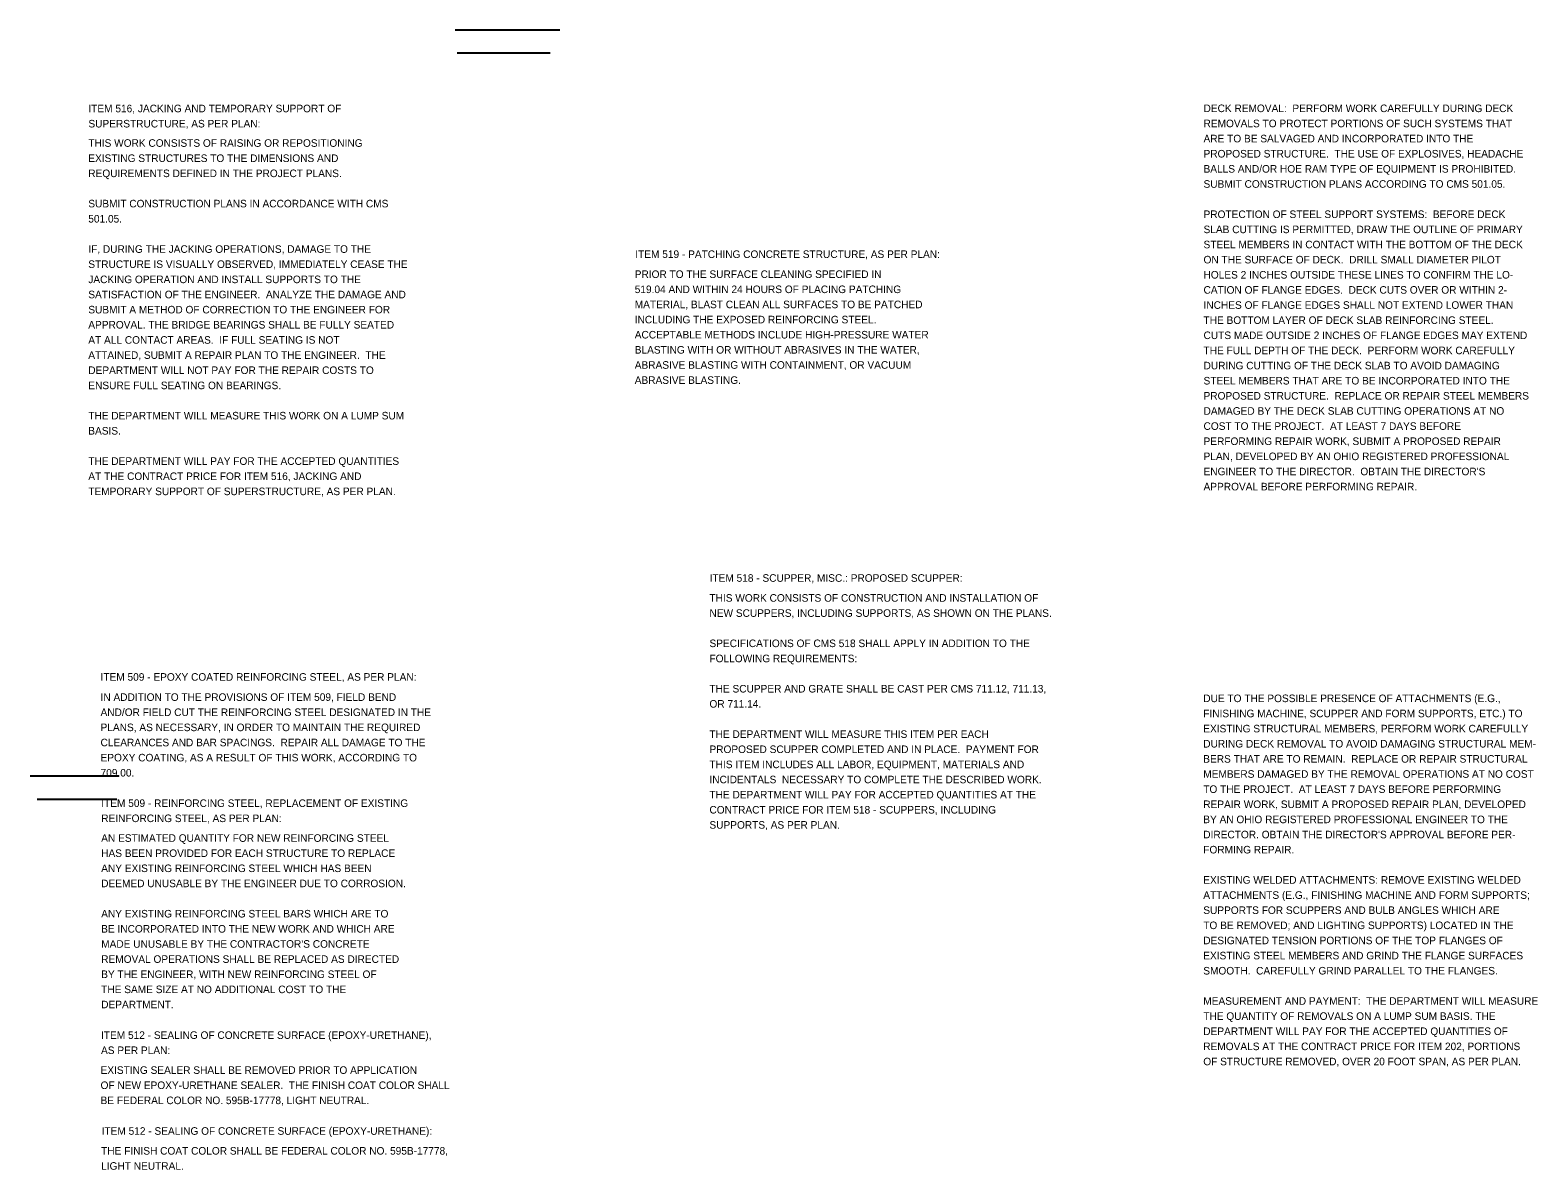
# Model space of a CAD drawing. Extents: x 8.9 to 72, y -18.6 to 3.4.
# Drawn here: x 44.1 to 72, y -17.7 to 3.39 of the extents above; entities that cross this region are included whole.
import ezdxf

# ---------------------------------------------------------------- set-up
doc = ezdxf.new("R2010")
doc.units = 0
doc.layers.add('BR_P_Gen_Text', color=7, linetype='Continuous')
doc.layers.add('SH_Text', color=7, linetype='Continuous')

msp = doc.modelspace()

# ---------------------------------------------------------------- linework, layer by layer
at = {"layer": 'BR_P_Gen_Text'}
for p, q in [((53.902, 3.39), (51.97, 3.39)), ((53.725, 2.963), (52.003, 2.963)), ((45.746, -10.413), (44.102, -10.413)), ((45.709, -10.844), (44.234, -10.844))]:
    msp.add_line(p, q, dxfattribs=at)

# ---------------------------------------------------------------- texts
for s, rotation, p in [('ITEM 516, JACKING AND TEMPORARY SUPPORT OF ', 0, (45.18, 1.871)), ('SUPERSTRUCTURE, AS PER PLAN:', 0, (45.18, 1.59)), ('THIS WORK CONSISTS OF RAISING OR REPOSITIONING ', 0, (45.178, 1.232)), ('EXISTING STRUCTURES TO THE DIMENSIONS AND ', 0, (45.178, 0.951)), ('REQUIREMENTS DEFINED IN THE PROJECT PLANS.', 0, (45.178, 0.671)), ('SUBMIT CONSTRUCTION PLANS IN ACCORDANCE WITH CMS ', 0, (45.178, 0.111)), ('501.05.', 0, (45.178, -0.17)), ('IF, DURING THE JACKING OPERATIONS, DAMAGE TO THE ', 0, (45.178, -0.73)), ('STRUCTURE IS VISUALLY OBSERVED, IMMEDIATELY CEASE THE ', 0, (45.178, -1.01)), ('PRIOR TO THE SURFACE CLEANING SPECIFIED IN ', 359.9999, (55.291, -1.195)), ('JACKING OPERATION AND INSTALL SUPPORTS TO THE ', 0, (45.178, -1.291)), ('519.04 AND WITHIN 24 HOURS OF PLACING PATCHING ', 359.9999, (55.291, -1.475)), ('SATISFACTION OF THE ENGINEER.  ANALYZE THE DAMAGE AND ', 0, (45.178, -1.571)), ('MATERIAL, BLAST CLEAN ALL SURFACES TO BE PATCHED ', 359.9999, (55.291, -1.755)), ('SUBMIT A METHOD OF CORRECTION TO THE ENGINEER FOR ', 0, (45.178, -1.851)), ('INCLUDING THE EXPOSED REINFORCING STEEL.  ', 359.9999, (55.291, -2.035)), ('APPROVAL. THE BRIDGE BEARINGS SHALL BE FULLY SEATED ', 0, (45.178, -2.131)), ('ACCEPTABLE METHODS INCLUDE HIGH-PRESSURE WATER ', 359.9999, (55.291, -2.315)), ('AT ALL CONTACT AREAS.  IF FULL SEATING IS NOT ', 0, (45.178, -2.412)), ('BLASTING WITH OR WITHOUT ABRASIVES IN THE WATER, ', 359.9999, (55.291, -2.595)), ('ATTAINED, SUBMIT A REPAIR PLAN TO THE ENGINEER.  THE ', 0, (45.178, -2.692)), ('ABRASIVE BLASTING WITH CONTAINMENT, OR VACUUM ', 359.9999, (55.291, -2.875)), ('DEPARTMENT WILL NOT PAY FOR THE REPAIR COSTS TO ', 0, (45.178, -2.972)), ('ABRASIVE BLASTING.', 359.9999, (55.291, -3.155)), ('ENSURE FULL SEATING ON BEARINGS.', 0, (45.178, -3.253)), ('THE DEPARTMENT WILL MEASURE THIS WORK ON A LUMP SUM ', 0, (45.178, -3.813)), ('BASIS.', 0, (45.178, -4.093)), ('THE DEPARTMENT WILL PAY FOR THE ACCEPTED QUANTITIES ', 0, (45.178, -4.654)), ('AT THE CONTRACT PRICE FOR ITEM 516, JACKING AND ', 0, (45.178, -4.934)), ('TEMPORARY SUPPORT OF SUPERSTRUCTURE, AS PER PLAN.', 0, (45.178, -5.214)), ('AN ESTIMATED QUANTITY FOR NEW REINFORCING STEEL ', 359.9999, (45.417, -11.629)), ('HAS BEEN PROVIDED FOR EACH STRUCTURE TO REPLACE ', 359.9999, (45.417, -11.909)), ('ANY EXISTING REINFORCING STEEL WHICH HAS BEEN ', 359.9999, (45.417, -12.189)), ('DEEMED UNUSABLE BY THE ENGINEER DUE TO CORROSION.', 359.9999, (45.417, -12.469)), ('ANY EXISTING REINFORCING STEEL BARS WHICH ARE TO ', 359.9999, (45.417, -13.029)), ('BE INCORPORATED INTO THE NEW WORK AND WHICH ARE ', 359.9999, (45.417, -13.309)), ("MADE UNUSABLE BY THE CONTRACTOR'S CONCRETE ", 359.9999, (45.417, -13.589)), ('REMOVAL OPERATIONS SHALL BE REPLACED AS DIRECTED ', 359.9999, (45.417, -13.869)), ('BY THE ENGINEER, WITH NEW REINFORCING STEEL OF ', 359.9999, (45.417, -14.149)), ('THE SAME SIZE AT NO ADDITIONAL COST TO THE ', 359.9999, (45.417, -14.429)), ('DEPARTMENT.', 359.9999, (45.417, -14.709))]:
    msp.add_text(s, height=0.14, rotation=rotation, dxfattribs=at).set_placement(p)
for s, p in [('DECK REMOVAL:  PERFORM WORK CAREFULLY DURING DECK', (65.818, 1.874)), ('REMOVALS TO PROTECT PORTIONS OF SUCH SYSTEMS THAT ', (65.818, 1.594)), ('ARE TO BE SALVAGED AND INCORPORATED INTO THE ', (65.818, 1.314)), ('PROPOSED STRUCTURE.  THE USE OF EXPLOSIVES, HEADACHE ', (65.818, 1.034)), ('BALLS AND/OR HOE RAM TYPE OF EQUIPMENT IS PROHIBITED.  ', (65.818, 0.754)), ('SUBMIT CONSTRUCTION PLANS ACCORDING TO CMS 501.05.', (65.818, 0.474)), ('PROTECTION OF STEEL SUPPORT SYSTEMS:  BEFORE DECK', (65.818, -0.086)), ('SLAB CUTTING IS PERMITTED, DRAW THE OUTLINE OF PRIMARY', (65.818, -0.366)), ('STEEL MEMBERS IN CONTACT WITH THE BOTTOM OF THE DECK', (65.818, -0.646)), ('ITEM 519 - PATCHING CONCRETE STRUCTURE, AS PER PLAN:', (55.301, -0.825)), ('ON THE SURFACE OF DECK.  DRILL SMALL DIAMETER PILOT', (65.818, -0.926)), ('HOLES 2 INCHES OUTSIDE THESE LINES TO CONFIRM THE LO-', (65.818, -1.206)), ('CATION OF FLANGE EDGES.  DECK CUTS OVER OR WITHIN 2-', (65.818, -1.486)), ('INCHES OF FLANGE EDGES SHALL NOT EXTEND LOWER THAN ', (65.818, -1.766)), ('THE BOTTOM LAYER OF DECK SLAB REINFORCING STEEL.  ', (65.818, -2.046)), ('CUTS MADE OUTSIDE 2 INCHES OF FLANGE EDGES MAY EXTEND ', (65.818, -2.326)), ('THE FULL DEPTH OF THE DECK.  PERFORM WORK CAREFULLY ', (65.818, -2.606)), ('DURING CUTTING OF THE DECK SLAB TO AVOID DAMAGING ', (65.818, -2.886)), ('STEEL MEMBERS THAT ARE TO BE INCORPORATED INTO THE ', (65.818, -3.166)), ('PROPOSED STRUCTURE.  REPLACE OR REPAIR STEEL MEMBERS ', (65.818, -3.446)), ('DAMAGED BY THE DECK SLAB CUTTING OPERATIONS AT NO ', (65.818, -3.726)), ('COST TO THE PROJECT.  AT LEAST 7 DAYS BEFORE ', (65.818, -4.006)), ('PERFORMING REPAIR WORK, SUBMIT A PROPOSED REPAIR ', (65.818, -4.286)), ('PLAN, DEVELOPED BY AN OHIO REGISTERED PROFESSIONAL', (65.818, -4.566)), ("ENGINEER TO THE DIRECTOR.  OBTAIN THE DIRECTOR'S ", (65.818, -4.846)), ('APPROVAL BEFORE PERFORMING REPAIR.', (65.818, -5.126)), ('ITEM 518 - SCUPPER, MISC.: PROPOSED SCUPPER:', (56.677, -6.817)), ('ITEM 509 - EPOXY COATED REINFORCING STEEL, AS PER PLAN:', (45.405, -8.648)), ('IN ADDITION TO THE PROVISIONS OF ITEM 509, FIELD BEND ', (45.405, -9.021)), ('DUE TO THE POSSIBLE PRESENCE OF ATTACHMENTS (E.G.,', (65.813, -9.044)), ('AND/OR FIELD CUT THE REINFORCING STEEL DESIGNATED IN THE ', (45.405, -9.301)), ('FINISHING MACHINE, SCUPPER AND FORM SUPPORTS, ETC.) TO', (65.813, -9.324)), ('PLANS, AS NECESSARY, IN ORDER TO MAINTAIN THE REQUIRED ', (45.405, -9.581)), ('EXISTING STRUCTURAL MEMBERS, PERFORM WORK CAREFULLY', (65.813, -9.604)), ('CLEARANCES AND BAR SPACINGS.  REPAIR ALL DAMAGE TO THE ', (45.405, -9.861)), ('DURING DECK REMOVAL TO AVOID DAMAGING STRUCTURAL MEM-', (65.813, -9.884)), ('EPOXY COATING, AS A RESULT OF THIS WORK, ACCORDING TO ', (45.405, -10.141)), ('BERS THAT ARE TO REMAIN.  REPLACE OR REPAIR STRUCTURAL', (65.813, -10.164)), ('709.00.', (45.405, -10.421)), ('MEMBERS DAMAGED BY THE REMOVAL OPERATIONS AT NO COST', (65.813, -10.444)), ('TO THE PROJECT.  AT LEAST 7 DAYS BEFORE PERFORMING', (65.813, -10.724)), ('ITEM 509 - REINFORCING STEEL, REPLACEMENT OF EXISTING', (45.418, -10.984)), ('REPAIR WORK, SUBMIT A PROPOSED REPAIR PLAN, DEVELOPED', (65.813, -11.004)), ('REINFORCING STEEL, AS PER PLAN:', (45.418, -11.264)), ('BY AN OHIO REGISTERED PROFESSIONAL ENGINEER TO THE', (65.813, -11.284)), ("DIRECTOR. OBTAIN THE DIRECTOR'S APPROVAL BEFORE PER-", (65.813, -11.564)), ('FORMING REPAIR.', (65.813, -11.844)), ('EXISTING WELDED ATTACHMENTS: REMOVE EXISTING WELDED', (65.813, -12.404)), ('ATTACHMENTS (E.G., FINISHING MACHINE AND FORM SUPPORTS;', (65.813, -12.684)), ('SUPPORTS FOR SCUPPERS AND BULB ANGLES WHICH ARE', (65.813, -12.964)), ('TO BE REMOVED; AND LIGHTING SUPPORTS) LOCATED IN THE', (65.813, -13.244)), ('DESIGNATED TENSION PORTIONS OF THE TOP FLANGES OF', (65.813, -13.524)), ('EXISTING STEEL MEMBERS AND GRIND THE FLANGE SURFACES', (65.813, -13.804)), ('SMOOTH.  CAREFULLY GRIND PARALLEL TO THE FLANGES.', (65.813, -14.084)), ('MEASUREMENT AND PAYMENT:  THE DEPARTMENT WILL MEASURE', (65.813, -14.644)), ('THE QUANTITY OF REMOVALS ON A LUMP SUM BASIS. THE', (65.813, -14.924)), ('DEPARTMENT WILL PAY FOR THE ACCEPTED QUANTITIES OF', (65.813, -15.204)), ('ITEM 512 - SEALING OF CONCRETE SURFACE (EPOXY-URETHANE),', (45.414, -15.276)), ('REMOVALS AT THE CONTRACT PRICE FOR ITEM 202, PORTIONS', (65.813, -15.484)), ('AS PER PLAN:', (45.414, -15.556)), ('OF STRUCTURE REMOVED, OVER 20 FOOT SPAN, AS PER PLAN.', (65.813, -15.764)), ('EXISTING SEALER SHALL BE REMOVED PRIOR TO APPLICATION', (45.405, -15.923)), ('OF NEW EPOXY-URETHANE SEALER.  THE FINISH COAT COLOR SHALL ', (45.405, -16.203)), ('BE FEDERAL COLOR NO. 595B-17778, LIGHT NEUTRAL.', (45.405, -16.483)), ('ITEM 512 - SEALING OF CONCRETE SURFACE (EPOXY-URETHANE):', (45.425, -17.05)), ('THE FINISH COAT COLOR SHALL BE FEDERAL COLOR NO. 595B-17778, ', (45.416, -17.417)), ('LIGHT NEUTRAL.', (45.416, -17.697))]:
    msp.add_text(s, height=0.14, dxfattribs=at).set_placement(p)
at = {"layer": 'SH_Text'}
for s, p in [('THIS WORK CONSISTS OF CONSTRUCTION AND INSTALLATION OF', (56.674, -7.186)), ('NEW SCUPPERS, INCLUDING SUPPORTS, AS SHOWN ON THE PLANS.', (56.674, -7.466)), ('SPECIFICATIONS OF CMS 518 SHALL APPLY IN ADDITION TO THE', (56.674, -8.026)), ('FOLLOWING REQUIREMENTS:', (56.674, -8.306)), ('THE SCUPPER AND GRATE SHALL BE CAST PER CMS 711.12, 711.13, ', (56.674, -8.866)), ('OR 711.14.', (56.674, -9.146)), ('THE DEPARTMENT WILL MEASURE THIS ITEM PER EACH', (56.674, -9.706)), ('PROPOSED SCUPPER COMPLETED AND IN PLACE.  PAYMENT FOR', (56.674, -9.986)), ('THIS ITEM INCLUDES ALL LABOR, EQUIPMENT, MATERIALS AND', (56.674, -10.266)), ('INCIDENTALS  NECESSARY TO COMPLETE THE DESCRIBED WORK.', (56.674, -10.546)), ('THE DEPARTMENT WILL PAY FOR ACCEPTED QUANTITIES AT THE', (56.674, -10.826)), ('CONTRACT PRICE FOR ITEM 518 - SCUPPERS, INCLUDING ', (56.674, -11.106)), ('SUPPORTS, AS PER PLAN. ', (56.674, -11.386))]:
    msp.add_text(s, height=0.14, dxfattribs=at).set_placement(p)

doc.saveas('drawing.dxf')
